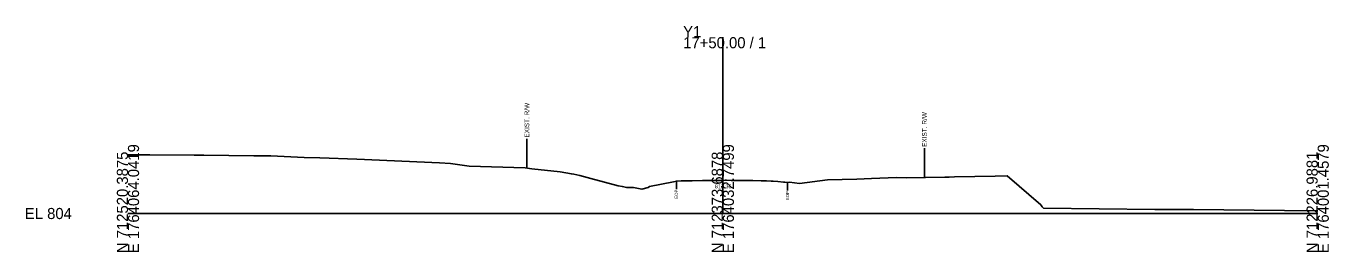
# Model space of a CAD drawing. Extents: x -26 to 1303, y -10 to 9524.
# Drawn here: x -25.7 to 302.8, y 7490.3 to 7547.3 of the extents above; entities that cross this region are included whole.
import ezdxf

# ---------------------------------------------------------------- set-up
doc = ezdxf.new("R2010")
doc.units = 0
for name, color, linetype in [('Default', 7, 'Continuous'), ('Exist Cross Section Cell', 7, 'Continuous'), ('Exist XS Center Line Elevation Label', 7, 'Continuous'), ('Exist XS Ground Line', 7, 'Continuous'), ('Old_Level_10', 7, 'Continuous')]:
    doc.layers.add(name, color=color, linetype=linetype)

msp = doc.modelspace()

# ---------------------------------------------------------------- linework, layer by layer
at = {"layer": 'Exist Cross Section Cell'}
for p, q in [((150, 7500), (150, 7544.47)), ((0, 7500), (150, 7500)), ((150, 7500), (300, 7500))]:
    msp.add_line(p, q, dxfattribs=at)
at = {"layer": 'Exist XS Ground Line'}
msp.add_lwpolyline([(0, 7514.81), (0.43, 7514.8), (5.56, 7514.82), (16.68, 7514.75), (19.11, 7514.71), (31.78, 7514.52), (36.05, 7514.54), (44.4, 7514.16), (48.38, 7514.03), (57.73, 7513.72), (78.54, 7512.75), (81.35, 7512.61), (86.07, 7511.9), (100.16, 7511.49), (101.86, 7511.28), (108.96, 7510.48), (111.83, 7509.99), (112.43, 7509.95), (113.91, 7509.59), (116.75, 7508.83), (123.58, 7507.01), (124.68, 7506.77), (125.74, 7506.55), (127.44, 7506.55), (129.6, 7506.14), (131.15, 7506.59), (131.54, 7506.79), (137.59, 7508.02), (138.28, 7508.17), (139.53, 7508.21), (140.2, 7508.23), (141.67, 7508.23), (142.27, 7508.24), (144.89, 7508.31), (145.21, 7508.31), (147.38, 7508.31), (149.1, 7508.35), (150, 7508.36), (150.62, 7508.37), (150.97, 7508.37), (152.12, 7508.36), (152.49, 7508.35), (153.32, 7508.33), (155.05, 7508.33), (157.19, 7508.29), (157.61, 7508.29), (159.64, 7508.25), (160.11, 7508.24), (161.01, 7508.22), (162.2, 7508.17), (162.72, 7508.16), (163.85, 7508.04), (165.27, 7507.91), (165.63, 7507.89), (166.3, 7507.83), (166.84, 7507.92), (169.37, 7507.57), (176.39, 7508.48), (183.77, 7508.67), (187.46, 7508.8), (193.82, 7509.06), (196.2, 7509.03), (205.99, 7509.14), (207.05, 7509.16), (208.38, 7509.21), (218.69, 7509.45), (221.73, 7509.54), (230.16, 7502.17), (230.56, 7501.69), (230.88, 7501.37), (258.92, 7501.03), (260.93, 7501.02), (268.71, 7501), (291.66, 7500.78), (300, 7500.66)], dxfattribs=at)
at = {"layer": 'Old_Level_10'}
for p, q in [((100.6, 7518.84), (100.6, 7511.43)), ((200.84, 7516.48), (200.84, 7509.08)), ((138.28, 7508.17), (138.28, 7506.12)), ((166.3, 7507.83), (166.3, 7505.78))]:
    msp.add_line(p, q, dxfattribs=at)

# ---------------------------------------------------------------- texts
at = {"layer": 'Default'}
msp.add_text('-', height=0.0001, dxfattribs=at).set_placement((0, 7500))
at = {"layer": 'Exist Cross Section Cell'}
for s, p in [('Y1', (140, 7544.47)), ('17+50.00 / 1', (140, 7541.67)), ('EL 804', (-26, 7498.6))]:
    msp.add_text(s, height=2.8, dxfattribs=at).set_placement(p)
for s, p in [('E 1764064.0419', (2.8, 7490)), ('E 1764032.7499', (152.8, 7490)), ('E 1764001.4579', (302.8, 7490)), ('N 712520.3875', (0, 7490)), ('N 712373.6878', (150, 7490)), ('N 712226.9881', (300, 7490))]:
    msp.add_text(s, height=2.8, rotation=90, dxfattribs=at).set_placement(p)
at = {"layer": 'Exist XS Center Line Elevation Label'}
msp.add_text('812.36', height=1, dxfattribs=at).set_placement((147.98, 7506.36))
at = {"layer": 'Old_Level_10'}
for s, height, p in [('EXIST. R/W', 1.181, (101.19, 7519.14)), ('EXIST. R/W', 1.181, (201.43, 7516.79)), ('EOP', 0.787, (138.67, 7503.73)), ('EOP', 0.787, (166.7, 7503.38))]:
    msp.add_text(s, height=height, rotation=90, dxfattribs=at).set_placement(p)

doc.saveas('drawing.dxf')
